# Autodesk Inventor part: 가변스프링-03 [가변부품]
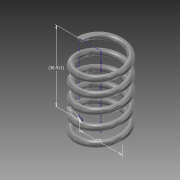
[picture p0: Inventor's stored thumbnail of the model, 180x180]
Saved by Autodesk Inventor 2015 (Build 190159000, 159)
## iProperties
Created: 2014-12
Part Number: 가변스프링-03 [가변부품]
Material: Steel, Carbon
Document SubType Name: Modeling
Designer: Deny
Density: 7.85 g/cm^3
Appearance: Semi-Polished
Mass: 18.8395 g
Surface Area: 32.544 cm^2
Volume: 2.39994 cm^3
Author: Deny
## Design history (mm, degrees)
sketch "Sketch1"
  geometry: L1 (0, 0)-(11, 0); L2 (11, 0)-(11, 36.411); L3 (11, 36.411)-(0, 36.411); L4 (0, 36.411)-(0, 0); C1 r 1.5 at (11, 0)
  constraints: 8 end point, 2 parallel, 1 centre point, 1 coincident, 1 horizontal, 1 perpendicular
  dimensions: "d0" = 3 diameter of C1; "d1" = 22 diameter of L2 L4; "d2" = 36.4112 distance between parallel lines of L1 L3 (derived)
coil "Coil1" sketch "Sketch1" pitch "d3" = 10; turns "d5" = 5; dims "d4" = 36.4112 (= d2), "d6" = 0, angle "d7" = 90 deg, angle "d8" = 90 deg, "d9" = 0, "d10" = 0
sketch "Sketch2"
  geometry: L1 (-12.5, 0)-(-9.5, 0) reference; 1 further point
  constraints: 1 horizontal alignment
extrude "Extrusion1" cut sketch "Sketch2" stored distance "d11" = 10; taper "d12" = 0 deg
workplane "Work Plane1"
sketch "Sketch3"
  geometry: L1 (1.5, 0)-(-1.5, 0) reference; 1 further point
  constraints: 1 horizontal alignment
extrude "Extrusion2" cut sketch "Sketch3" stored distance "d14" = 10; taper "d15" = 0 deg
body "Solid1"
node "Project Cut Edges1"
node "Project Cut Edges2"
other parameters: "d13" = 0
